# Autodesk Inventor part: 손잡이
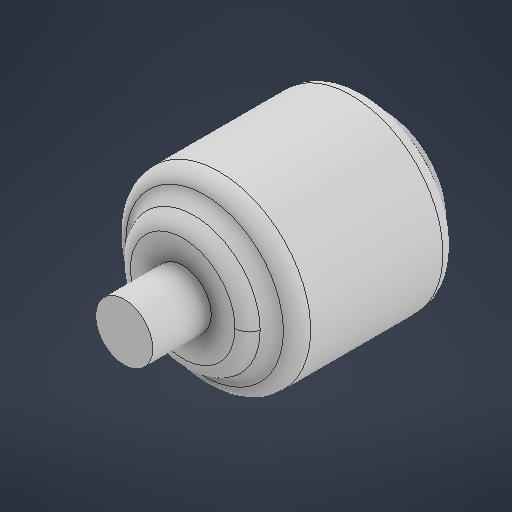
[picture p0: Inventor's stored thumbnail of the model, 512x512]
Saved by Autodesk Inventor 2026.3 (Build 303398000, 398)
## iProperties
Created: 2026-08
Part Number: 손잡이
Material: 일반
Document SubType Name: Modeling
Designer: chang
Density: 1 g/cm^3
Appearance: 기본값
Author: chang
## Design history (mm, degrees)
sketch "스케치1"
  geometry: C1 r 9 at (0, 0); 1 further point
  constraints: 1 centre point, 1 coincident
  dimensions: "d0" = 18 diameter of C1
extrude "돌출1" new body sketch "스케치1" distance "d1" = 3; taper "d2" = 0 deg
sketch "스케치2"
  geometry: C1 r 12.5 at (0, 0); 1 further point
  constraints: 1 centre point, 1 coincident
  dimensions: "d3" = 25 diameter of C1
extrude "돌출2" join sketch "스케치2" distance "d4" = 22; taper "d5" = 0 deg
sketch "스케치3"
  geometry: C1 r 9 at (0, 0); 1 further point
  constraints: 1 centre point, 1 coincident
  dimensions: "d6" = 18 diameter of C1
extrude "돌출3" join sketch "스케치3" distance "d7" = 3; taper "d8" = 0 deg
feature "면 모깎기1" dims "d9" = 2
feature "면 모깎기2" dims "d10" = 2
fillet "모깎기1" dims "d11" = 2
fillet "모깎기2" dims "d12" = 2
fillet "모깎기3" dims "d13" = 2
fillet "모깎기4" dims "d14" = 2
sketch "스케치4"
  geometry: C1 r 3.9 at (0, 0); 1 further point
  constraints: 1 centre point, 1 coincident
  dimensions: "d15" = 7.8 diameter of C1
extrude "돌출4" join sketch "스케치4" distance "d16" = 8; taper "d17" = 0 deg
node "솔리드1"
